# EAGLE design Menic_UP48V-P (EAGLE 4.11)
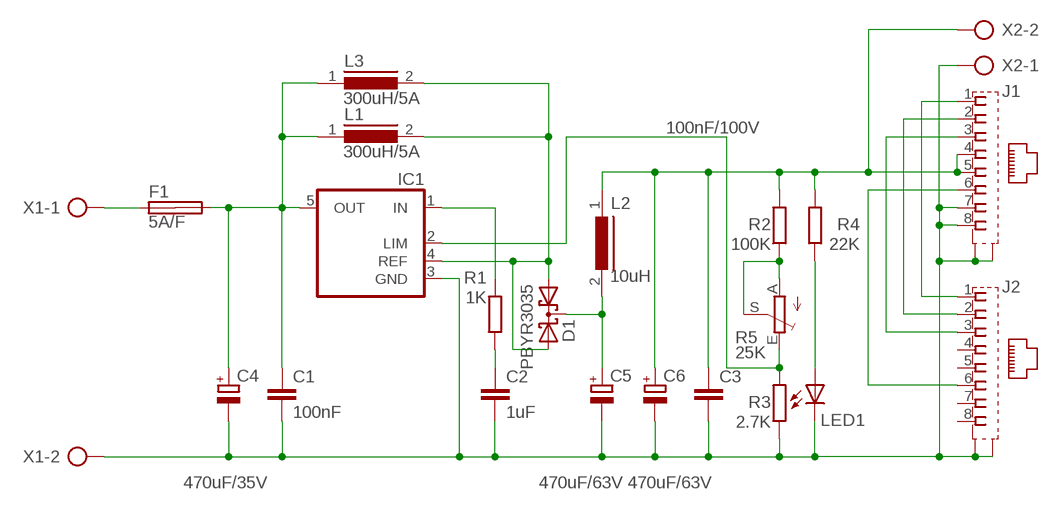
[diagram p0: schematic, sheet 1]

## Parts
C1  100nF  C-EU025_050-025X075  [C025_050-025X075]
C2  1uF  C-EU025_050-025X075  [C025_050-025X075]
C3  100nF/100V  C-EU025_050-025X075  [C025_050-025X075]
C4  470uF/35V  CPOL-EUE5-10.5  [E5-10,5]
C5  470uF/63V  CPOL-EUE5-10.5  [E5-10,5]
C6  470uF/63V  CPOL-EUE5-10.5  [E5-10,5]
D1  PBYR3035  [SOT93S]
F1  5A/F  SHK20L  [SHK20L]
IC1  L200  [L200S]
J1  556591-1  [556591-1]
J2  556591-1  [556591-1]
L1  300uH/5A  SFT1240  [SFT1240]
L2  10uH  82114R  [82114R]
L3  300uH/5A  SFT1240  [SFT1240]
LED1  LED3MM  [LED3MM]
R1  1K  R-EU_0207/10  [0207/10]
R2  100K  R-EU_0207/10  [0207/10]
R3  2.7K  R-EU_0207/10  [0207/10]
R4  22K  R-EU_0207/10  [0207/10]
R5  25K  TRIM_EU-CA6V  [CA6V]
X1  AK500/2  [AK500/2]
X2  AK500/2  [AK500/2]

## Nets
N$1: F1.1A X1.1
N$2: J1.1 J2.1
N$3: C1.1 C4.+ F1.2A IC1.5(OUT) L1.1 L3.1
N$6: IC1.1(IN) R1.2
N$7: C2.1 R1.1
N$8: C5.+ D1.C L2.2
N$9: LED1.A R4.1
N$11: R2.1 R5.A R5.S
N$12: IC1.2(LIM) R3.2 R5.E
N$13: J1.2 J2.2
N$14: C1.2 C2.2 C3.2 C4.- C5.- C6.- IC1.3(GND) J1.7 J1.8 J1.G1(S1) J1.G2(S2) J2.G1(S1) J2.G2(S2) LED1.K(C) R3.1 X1.2 X2.1
N$15: J1.3 J2.3
N$16: J1.6 J2.6
N$19: C3.1 C6.+ J1.4 J1.5 L2.1 R2.2 R4.2 X2.2
N$25: D1.A1 D1.A2 IC1.4(REF) L1.2 L3.2
Unconnected: F1.1B F1.2B J2.4 J2.5 J2.7 J2.8

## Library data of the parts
C1-C3 = rcl:C-EU: CAPACITOR, European symbol
C4-C6 = rcl:CPOL-EU: POLARIZED CAPACITOR, European symbol
D1 = diode:PBYR3035: Dual DIODE common cathode
F1 = fuse:SHK20L: FUSE HOLDER 5 x 20 mm, SH contact, SHH1 Schukat, E1073 Buerklin
IC1 = v-reg:L200: VOLTAGE REGULATOR
J1 J2 = con-amp:556591-1: AMP connector
L1 L3 = inductors:SFT1240: INDUCTOR
L2 = inductors:82114R: INDUCTOR
LED1 = led:LED: LED
R1-R4 = rcl:R-EU_: RESISTOR, European symbol
R5 = pot:TRIM_EU-: POTENTIOMETER
X1 X2 = con-ptr500:AK500/2: CONNECTOR

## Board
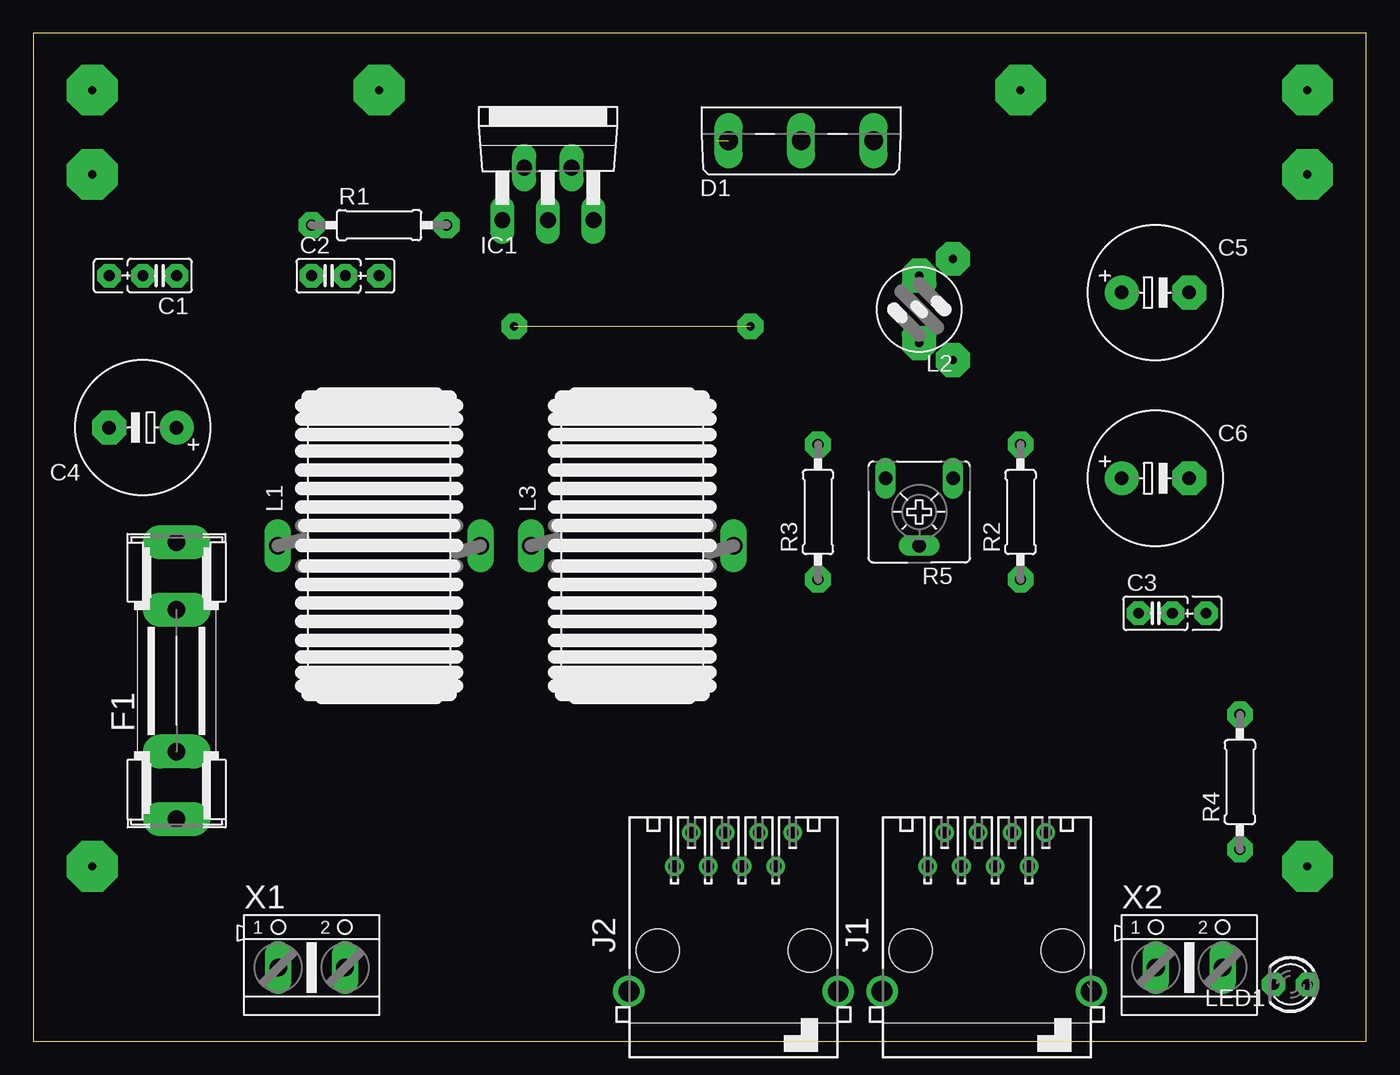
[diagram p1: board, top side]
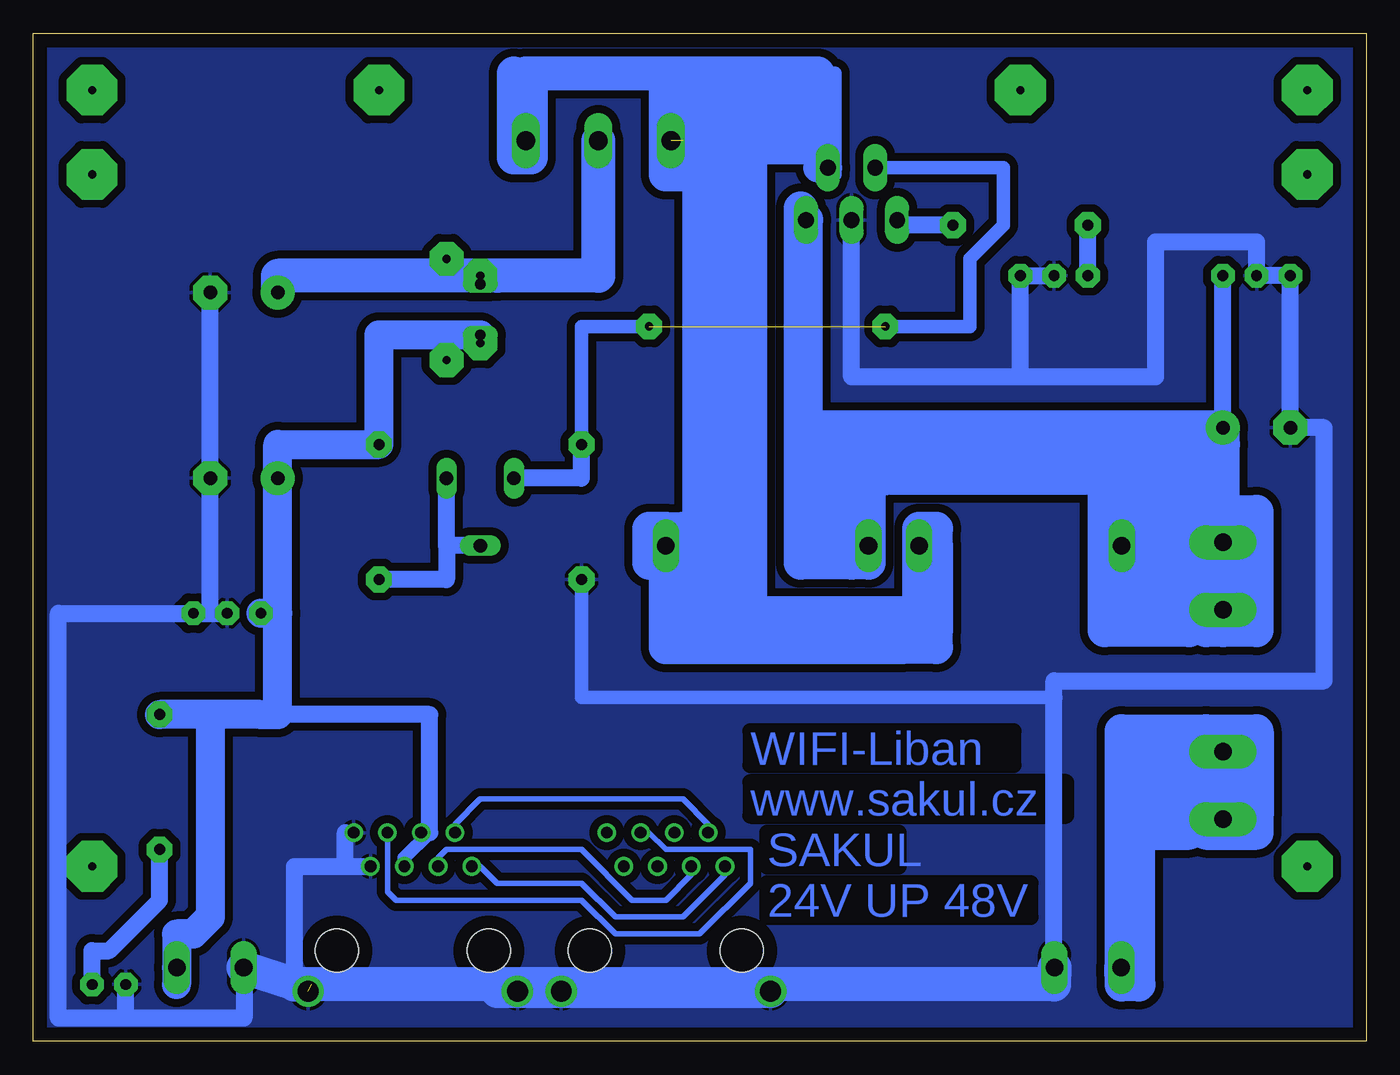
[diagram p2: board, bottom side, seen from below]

Size 100.31 x 75.87 mm. Coordinates in mm from the lower left corner, seen from the top.
Outline: 0,0 100.31,0 100.31,75.87 0,75.87 0,0
Copper layers (1*16): Top 0.035mm / dielectric 1.5mm / Bottom 0.035mm
Design rules "default": minimum track width 10mil, minimum drill 24mil, track to track 8mil, track to pad 8mil, pad to pad 8mil, via to via 8mil, smd to smd 8mil, copper to edge 40mil, drill to drill 8mil, minimum pad ring 10mil, minimum via ring 8mil, stop-mask expansion 4mil, vias tented up to drill 0mil, thermal gap 10mil

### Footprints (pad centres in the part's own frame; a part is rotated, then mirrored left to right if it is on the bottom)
C025_050-025X075 = drill 0.813 pad 1.778 octagon: 1 -1.27,0; 2 1.27,0; 3 3.81,0
E5-10,5 = drill 1.016 pad 2.54 round: + -2.54,0 | drill 1.016 pad 2.54 octagon: - 2.54,0
SOT93S = drill 1.397 long: A1 -5.461,-2.54; A2 5.461,-2.54; C 0,-2.54
SHK20L = drill 1.321 pad 2.54 long: 1A -10.414,0; 1B -5.334,0; 2A 10.414,0; 2B 5.334,0
L200S = drill 1.194 long: 1 -3.429,-8.509; 2 -1.778,-4.572; 3 0,-8.509; 4 1.778,-4.572; 5 3.429,-8.509
556591-1 = drill 0.889 round: 1 -4.445,6.35; 2 -3.175,8.89; 3 -1.905,6.35; 4 -0.635,8.89; 5 0.635,6.35; 6 1.905,8.89; 7 3.175,6.35; 8 4.445,8.89 | drill 1.575 pad 2.184 round: G1 -7.874,-3.048; G2 7.874,-3.048 | hole 3.251: -5.715,0; 5.715,0
SFT1240 = drill 1.321 long: 1 -7.62,0; 2 7.62,0
82114R = drill 0.813 long: 1 0,1.905; 2 0,-1.905
LED3MM = drill 0.813 pad 1.778 octagon: A -1.27,0; K 1.27,0
0207/10 = drill 0.813 pad 1.93 octagon: 1 -5.08,0; 2 5.08,0
CA6V = drill 1.016 long: A -2.54,-2.54; E 2.54,-2.54; S 0,2.54
AK500/2 = drill 1.321 long: 1 -2.515,0; 2 2.515,0

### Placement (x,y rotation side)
C1  9.52,57.62 180 top
C2  22.22,57.62 0 top
C3  84.45,32.22 0 top
C4  8.25,46.19 180 top
C5  84.45,56.35 0 top
C6  84.45,42.38 0 top
D1  57.78,70.32 0 top
F1  10.79,27.14 90 top
IC1  38.73,70.32 0 top
J1  71.75,6.82 0 top
J2  52.7,6.82 0 top
L1  26.03,37.3 0 top
L2  66.67,55.08 180 top
L3  45.08,37.3 0 top
LED1  94.61,4.28 180 top
R1  26.03,61.43 0 top
R2  74.29,39.84 90 top
R3  59.05,39.84 90 top
R4  90.8,19.52 90 top
R5  66.67,39.84 180 top
X1  20.95,5.55 0 top
X2  86.99,5.55 0 top

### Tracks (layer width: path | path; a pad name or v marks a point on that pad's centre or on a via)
N$1
  Bottom 2.54: 18.41,4.28 X1.1 | 18.41,16.98 12.06,16.98 | 12.06,16.98 10.79,16.98 | 9.52,16.98 8.25,16.98 8.25,22.06 | 8.25,22.06 8.25,23.33 12.06,23.33 | 12.06,16.98 12.06,23.33 | 12.06,16.98 12.06,15.71 8.25,15.71 8.25,22.06 | 8.25,22.06 9.52,22.06 | 9.52,22.06 10.79,22.06 10.79,16.98 | 9.52,16.98 9.52,22.06 | 10.79,16.98 9.52,16.98 | 10.79,16.98 F1.1A | 12.06,23.33 18.41,23.33 18.41,16.98 | 18.41,16.98 15.87,19.52 15.87,22.06 17.14,20.79 13.33,20.79 | 13.33,20.79 13.33,22.06 | 13.33,20.79 13.33,18.25 14.6,18.25 14.6,16.98 13.33,15.71 17.14,15.71 17.14,4.28 18.41,4.28 | 18.41,4.28 18.41,6.82 18.41,16.98
N$2
  Bottom 0.406: J1.1 66.67,13.17 65.4,11.9 59.05,11.9 56.51,9.36 51.43,9.36 48.26,12.54 J2.1
N$3
  Bottom 1.27: C4.+ C1.1
  Bottom 2.54: 10.79,30.95 F1.2A | 10.79,30.95 12.06,30.95 12.06,37.3 | 8.25,38.57 12.06,38.57 | 8.25,38.57 8.25,30.95 10.79,30.95 | 10.79,30.95 10.79,39.84 | 8.25,38.57 8.25,39.84 10.79,39.84 | 10.79,39.84 12.06,39.84 | 12.06,38.57 12.06,39.84 | 12.06,37.3 12.06,36.03 18.41,36.03 L1.1 | L1.1 18.41,38.57 12.06,38.57 | 12.06,38.57 12.06,37.3 | 12.06,37.3 L1.1 | 10.79,39.84 10.79,44.92 | 10.79,44.92 C4.+ 40,46.19 | 37.46,36.03 L3.1 | 37.46,36.03 38.73,36.03 | 38.73,36.03 38.73,39.84 37.46,39.84 37.46,36.03 | 37.46,43.65 37.46,36.03 | 37.46,43.65 18.41,43.65 18.41,42.38 | 18.41,42.38 18.41,39.84 12.06,39.84 | IC1.5 42.16,43.65 42.54,43.65 42.54,41.11 | 41.27,41.11 42.54,41.11 | 41.27,43.65 38.73,43.65 38.73,41.11 41.27,41.11 | 41.27,43.65 41.27,41.11 | 37.46,43.65 41.27,43.65 | 42.54,41.11 42.54,62.7 | 10.79,44.92 19.68,44.92 | 19.68,44.92 41.27,44.92 | 19.68,44.92 17.14,42.38 | 17.14,42.38 15.87,41.11 12.06,41.11 12.06,43.65 14.6,43.65 | 14.6,43.65 15.87,42.38 17.14,42.38 | 17.14,42.38 15.87,43.65 14.6,43.65 | 14.6,43.65 13.33,42.38 13.33,30.95 19.68,30.95 19.68,33.49 | 19.68,33.49 19.68,42.38 | 19.68,33.49 18.41,32.22 14.6,32.22 14.6,34.76 15.87,34.76 17.14,33.49 18.41,34.76 | 38.73,36.03 42.54,36.03 42.54,41.11 | 42.54,41.11 40,38.57 41.27,37.3 | 40,46.19 41.27,46.19 | 40,46.19 36.19,42.38 18.41,42.38
N$4  (via drill 0.61 pad 3.81)
  other vias: 95.88,13.17
N$6
  Bottom 1.27: IC1.1 35.3,61.43 R1.2
N$7
  Bottom 1.27: C2.1 R1.1
N$8  (via drill 0.61 pad 2.54)
  Bottom 1.016: L2.2 66.03,56.98 65.4,57.62
  Bottom 2.54: D1.C 57.78,57.62 65.4,57.62 v66.67,57.62 81.91,57.62 C5.+
N$9
  Bottom 1.27: LED1.A 95.88,6.82 94.61,6.82 90.8,10.63 R4.1
N$10  (via drill 0.61 pad 3.81)
  other vias: 4.44,13.17
N$11
  Bottom 1.27: 69.21,37.3 R5.A | R5.S 69.21,37.3 | R2.1 69.21,34.76 69.21,37.3
N$12  (1 unrouted)
  Bottom 1.016: IC1.2 27.3,65.75 27.3,61.43 29.84,58.89 29.84,53.81 36.19,53.81 | R3.2 59.05,53.81 53.97,53.81
  Bottom 1.27: R3.2 59.05,42.38 R5.E
N$13
  Bottom 0.406: J1.2 68.57,16.34 66.67,18.25 51.43,18.25 49.53,16.34 J2.2
N$14  (1 unrouted)
  Bottom 1.016: R3.1 59.05,25.87 23.49,25.87
  Bottom 1.27: 26.03,50 26.03,57.62 C2.2 | IC1.3 38.73,50 26.03,50 | 26.03,50 15.87,50 15.87,60.16 8.25,60.16 C1.2 5.71,57.62 C4.- 3.17,46.19 3.17,27.14 23.49,27.14 23.49,25.87 23.49,4.28 | 86.99,32.22 C3.2 98.42,32.22 98.42,1.74 93.34,1.74 | 86.99,32.22 88.26,32.22 | 86.99,32.22 C6.- C5.- | 76.83,13.17 80.64,13.17 80.64,4.28 | 76.83,13.17 J1.7 | 93.34,1.74 LED1.K | 93.34,1.74 84.45,1.74 84.45,5.55 X2.1 | J1.8 76.83,15.71 76.83,13.17
  Bottom 2.54: X1.2 23.49,4.28 45.08,4.28 | 47.62,4.28 60.32,4.28 | 60.32,4.28 62.86,4.28 | 62.86,4.28 65.4,4.28 | 65.4,4.28 79.37,4.28 80.64,4.28 X2.1 | 65.4,4.28 65.4,3.77 J1.G1 J2.G2 | 60.32,3.77 J2.G2 | 60.32,4.28 60.32,3.77 | J2.G2 62.86,3.77 62.86,4.28 | 60.32,3.77 45.08,3.77 45.08,4.28 | 45.08,4.28 47.62,4.28 | J2.G1 44.83,4.28 47.62,4.28
  pour Bottom (isolate 0.61): 0.63,75.4 99.69,75.4 99.69,0.47 0.63,0.47
N$15
  Bottom 0.406: J1.3 69.84,13.81 69.21,14.44 59.05,14.44 55.24,10.63 52.7,10.63 50.8,12.54 J2.3
N$16
  Bottom 0.406: J2.6 53.97,15.71 52.7,14.44 46.35,14.44 46.35,11.9 50.16,8.09 56.51,8.09 59.05,10.63 73.02,10.63 73.66,11.27 J1.6
N$17  (via drill 0.61 pad 3.81)
  other vias: 4.44,65.24
N$18  (via drill 0.61 pad 3.81)
  other vias: 95.88,65.24
N$19
  Bottom 1.016: J1.5 72.38,13.81 70.48,15.71
  Bottom 1.27: J1.4 70.48,15.71 70.48,24.6 83.18,24.6
  Bottom 2.184: 89.53,5.55 X2.2 | 89.53,5.55 89.53,4.28 | 89.53,5.55 89.53,8.09 88.26,8.09 86.99,9.36 86.99,24.6 | 86.99,24.6 R4.2 | L2.1 74.29,53.17 R2.2 81.91,44.92 C6.+ 81.91,32.22 | 81.91,32.22 81.91,24.6 83.18,24.6 86.99,24.6 | 81.91,32.22 C3.1
N$20  (via drill 0.61 pad 3.81)
  other vias: 74.29,71.59
N$21  (via drill 0.61 pad 3.81)
  other vias: 26.03,71.59
N$22  (via drill 0.61 pad 1.93)
  other vias: 36.19,53.81
N$23  (via drill 0.61 pad 1.93)
  other vias: 53.97,53.81
N$25  (1 unrouted)
  Bottom 1.016: 42.54,72.86 41.27,72.86 40,72.86 40,65.24 41.27,65.24 41.27,66.51 46.35,66.51
  Bottom 2.184: IC1.4 41.27,65.75 41.27,66.51 41.27,71.59 | 50.16,71.59 42.54,71.59 | 62.86,72.86 63.24,72.86
  Bottom 2.54: 52.7,71.59 52.7,65.24 50.16,65.24 | 47.62,67.78 47.62,32.22 48.89,32.22 48.89,69.05 | 52.7,38.57 L3.2 | 52.7,38.57 51.43,38.57 51.43,36.03 53.97,36.03 53.97,38.57 52.7,38.57 | 52.7,30.95 52.7,38.57 | 52.7,29.68 52.7,30.95 | 52.7,30.95 34.92,30.95 | 34.92,30.95 33.65,30.95 33.65,32.22 | 33.65,32.22 L1.2 33.65,38.57 32.38,38.57 32.38,37.3 | 32.38,37.3 32.38,30.95 34.92,30.95 | 34.92,30.95 34.92,29.68 52.7,29.68 | 52.7,29.68 32.38,29.68 32.38,37.3 | 63.24,72.86 D1.A2 | 50.16,72.86 51.43,72.86 51.43,67.78 | 50.16,70.32 50.16,71.59 | 50.16,70.32 50.16,69.05 48.89,69.05 | 42.54,70.32 42.54,69.05 | 42.54,70.32 41.27,70.32 | 50.16,70.32 42.54,70.32 | 50.16,65.24 50.16,32.22 52.7,32.22 52.7,30.95 | 50.16,65.24 50.16,67.78 | 50.16,67.78 50.16,70.32 | 50.16,67.78 D1.A1 | 42.54,69.05 48.89,69.05 | 42.54,69.05 41.27,67.78 46.35,67.78 46.35,66.51 46.35,32.22 33.65,32.22 | 62.86,72.86 41.27,72.86 41.27,71.59
N$26
  Bottom 2.54: 62.86,71.59 64.13,72.86 64.13,66.51 62.86,66.51 62.86,71.59
N$27  (via drill 0.61 pad 3.81)
  other vias: 4.44,71.59
N$28  (via drill 0.61 pad 3.81)
  other vias: 95.88,71.59
N$29  (via drill 0.61 pad 2.54)
  other vias: 66.67,52.54
N$30  (via drill 0.61 pad 2.54)
  other vias: 69.21,58.89
N$31  (via drill 0.61 pad 2.54)
  other vias: 69.21,51.27

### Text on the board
Bottom: WIFI-Liban | www.sakul.cz | SAKUL | 24V UP 48V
